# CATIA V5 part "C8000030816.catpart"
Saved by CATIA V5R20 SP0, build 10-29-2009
Part number: C8000030816
Source: Unknown
Property "A": "30"
Property "ARTICLENO": "C8000030816"
Property "B": "13"
Property "BOMINFO": "C8000030816"
Property "C": "46"
Property "CA": "C8000030816"
Property "D1": "38"
Property "DES": "ROTATING EYEBOLT WITH RING Ton 0,3 M8x16"
Property "E": "50"
Property "H": "105"
Property "L": "16"
Property "LINA": "C8000030816"
Property "NB": "C8000030816"
Property "NBSYN": "$CODE."
Property "NN": "C800"
Property "NT": "Rotating eyebolt with ring"
Property "SIZE": "M8"
Property "SUPPLIER": "CF"
Property "SW": "30"
Property "WEIGHT": "480"
Property "WLL": "0.30"
Bounding box of the stored display mesh (mm): x -27.837 to 28, y -16 to 117.837, z -19 to 19
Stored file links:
  C:\Users\Utente\Desktop\3D files 800\C8000030816.catpart
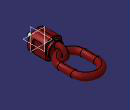
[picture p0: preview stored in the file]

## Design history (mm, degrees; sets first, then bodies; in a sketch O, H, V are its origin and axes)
Body1 "Geometry.1" (main body)
  Solid1 "C8000030816.catpart": solid without history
